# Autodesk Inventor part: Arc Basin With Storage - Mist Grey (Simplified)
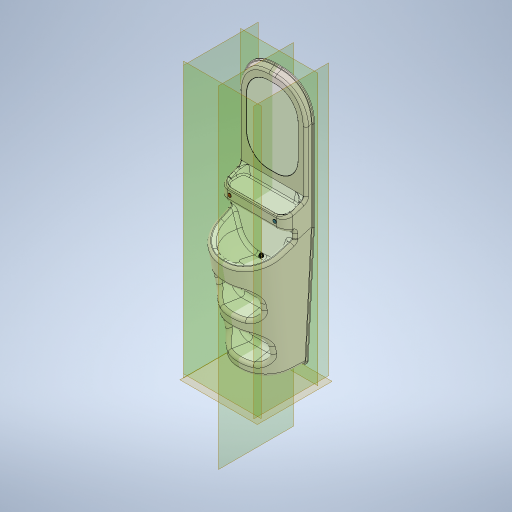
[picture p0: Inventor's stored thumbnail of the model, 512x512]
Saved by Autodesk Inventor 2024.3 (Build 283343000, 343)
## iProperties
Created: 2024-07
Part Number: Arc Basin With Storage - Mist Grey (Simplified)
Material: Generic
Document SubType Name: Modeling
Designer: Brian.Thangei
Density: 1 g/cm^3
Appearance: Default
Author: Brian.Thangei
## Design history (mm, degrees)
derived "Assembly9.iam"
workplane "Work Plane1"
workplane "Work Plane2"
workplane "Work Plane3"
workplane "Work Plane4"
body "Solid1"
node "PCPD1797-00 - Pineapple Onvo Sink - UK with storage - full a"
body "Srf1"
body "Srf2"
feature "Srf1::Derived"
feature "Srf2::Derived"
other parameters: "d1" = 0
